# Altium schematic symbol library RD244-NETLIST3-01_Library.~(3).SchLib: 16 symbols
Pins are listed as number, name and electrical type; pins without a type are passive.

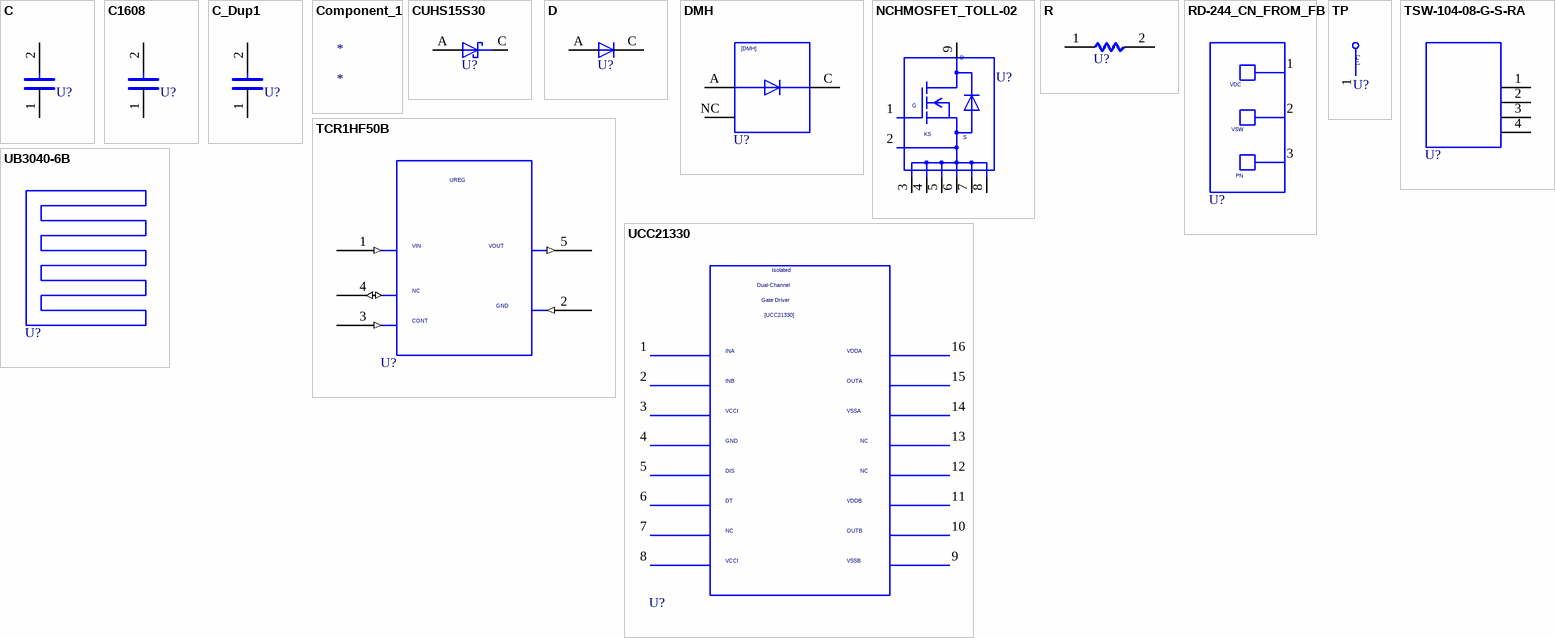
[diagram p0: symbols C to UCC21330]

## C
designator U?  (value not drawn)
OriginalSymbolOrigin: (2540,7620); Altium-Right: 20; Altium-Bottom: 10
pins: 1, 2

## C1608
designator U?  (value not drawn)
TIME: 10:25:11; UPDATEUSER: t4887876; UPDATETIME: 06:19:09; SAVECOUNT: 10; VAL3: xx型名を手入力; VAL1: xxF(x); VAL2: xxV; CHIPSET: 1608; OriginalSymbolOrigin: (2540,7620); Altium-Right: 20
pins: 1, 2

## C_Dup1
designator U?, comment C  (value not drawn)
OriginalSymbolOrigin: (2540,7620); Altium-Right: 20; Altium-Bottom: 10
pins: 1, 2

## Component_1
designator *

## CUHS15S30
designator U?  (value not drawn)
SAVEAREA0: -4630,-153,17114,13055; TIME: 14:49:55; UPDATEUSER: t4887876; UPDATETIME: 17:19:09; SAVECOUNT: 10; OriginalSymbolOrigin: (5080,5080); Altium-Right: 20
pins: A, C

## D
designator U?  (value not drawn)
SAVEAREA0: -225,-91,12804,7836; SAVECOUNT: 3; TIME: 14:49:55; UPDATEUSER: 19870035; UPDATETIME: 14:20:16; OriginalSymbolOrigin: (5080,5080); Altium-Right: 10; Altium-Bottom: 20
pins: A, C

## DMH
designator U?  (value not drawn)
SAVEAREA0: -4931,-287,27399,20979; TIME: 08:58:08; UPDATEUSER: kishi-s; UPDATETIME: 09:01:52; SAVECOUNT: 2; OriginalSymbolOrigin: (5080,17780); Altium-Right: 50; Altium-Bottom: 60
pins: A, C, NC

## NCHMOSFET_TOLL-02
designator U?  (value not drawn)
PARTS: 1; CLASS: DISCRETE; PKG_TYPE: DISC; LEVEL: STD; DEVICENAME: 2SJ132; SAVECOUNT: 33; SAVEAREA0: -7753,-3954,18724,15429; TIME: 17:22:02; UPDATEUSER: t5459927; UPDATETIME: 20:09:04; COMP: NchMOSFET_TOLL-01; CHIPSET: TOLL; VAL3: ※型名を記入する(TOLL); VAL1: ※定格電圧を記入する; VAL2: ※定格電流を記入する; OriginalSymbolOrigin: (0,22860); Altium-Right: 70; Altium-Bottom: 80
pins: 1, 2, 3, 4, 5, 6, 7, 8, 9

## R
designator U?  (value not drawn)
OriginalSymbolOrigin: (5080,5080); Altium-Right: 20
pins: 1, 2

## RD-244_CN_FROM_FB
designator U?, comment RD-244_CN_from_FB  (value not drawn)
TIME: 11:34:46; UPDATEUSER: t5459927; UPDATETIME: 14:01:19; SAVECOUNT: 38; SAVEAREA0: -20981,-344,43891,33349; VAL3: PCB_Pad; OriginalSymbolOrigin: (0,25400); Altium-Right: 50; Altium-Bottom: 100
pins: 1, 2, 3

## TCR1HF50B
designator U?  (value not drawn)
SAVEAREA0: -444,-3509,43701,41525; TIME: 18:31:00; UPDATEUSER: t6860224; UPDATETIME: 18:26:20; SAVECOUNT: 21; VAL1: Linear Regulator; OriginalSymbolOrigin: (7620,35560); Altium-Right: 110; Altium-Bottom: 130
pins: 1 (in), 2 (in), 3 (in), 4 (io), 5 (out)

## TP
designator U?  (value not drawn)
TIME: 16:12:21; UPDATEUSER: fukuda-y; UPDATETIME: 16:18:11; SAVECOUNT: 2; SAVEAREA0: -242,-92,12810,7836; OriginalSymbolOrigin: (0,7620); Altium-Right: 20; Altium-Bottom: 30
pins: 1

## TSW-104-08-G-S-RA
designator U?  (value not drawn)
SAVEAREA0: -8845,-265,28754,23475; SAVECOUNT: 24; TIME: 13:28:28; UPDATEUSER: t4887876; UPDATETIME: 10:06:27; OriginalSymbolOrigin: (2540,20320); Altium-Right: 50; Altium-Bottom: 70
pins: 1, 2, 3, 4

## UB3040-6B
designator U?  (value not drawn)
TIME: 14:03:26; UPDATEUSER: t4887876; UPDATETIME: 11:08:23; SAVECOUNT: 67; SAVEAREA0: -22316,-9081,43667,39223; VAL2: W30mm*L40mm*H6mm; OriginalSymbolOrigin: (5080,21590); Altium-Right: 80; Altium-Bottom: 90

## UCC21330
designator U?  (value not drawn)
SAVEAREA0: -23586,-777,74646,64019; SAVECOUNT: 95; TIME: 14:04:55; UPDATEUSER: t4887876; UPDATETIME: 15:12:35; OriginalSymbolOrigin: (-2540,55880); Altium-Right: 220
pins: 1, 2, 3, 4, 5, 6, 7, 8, 9, 10, 11, 12, 13, 14, 15, 16

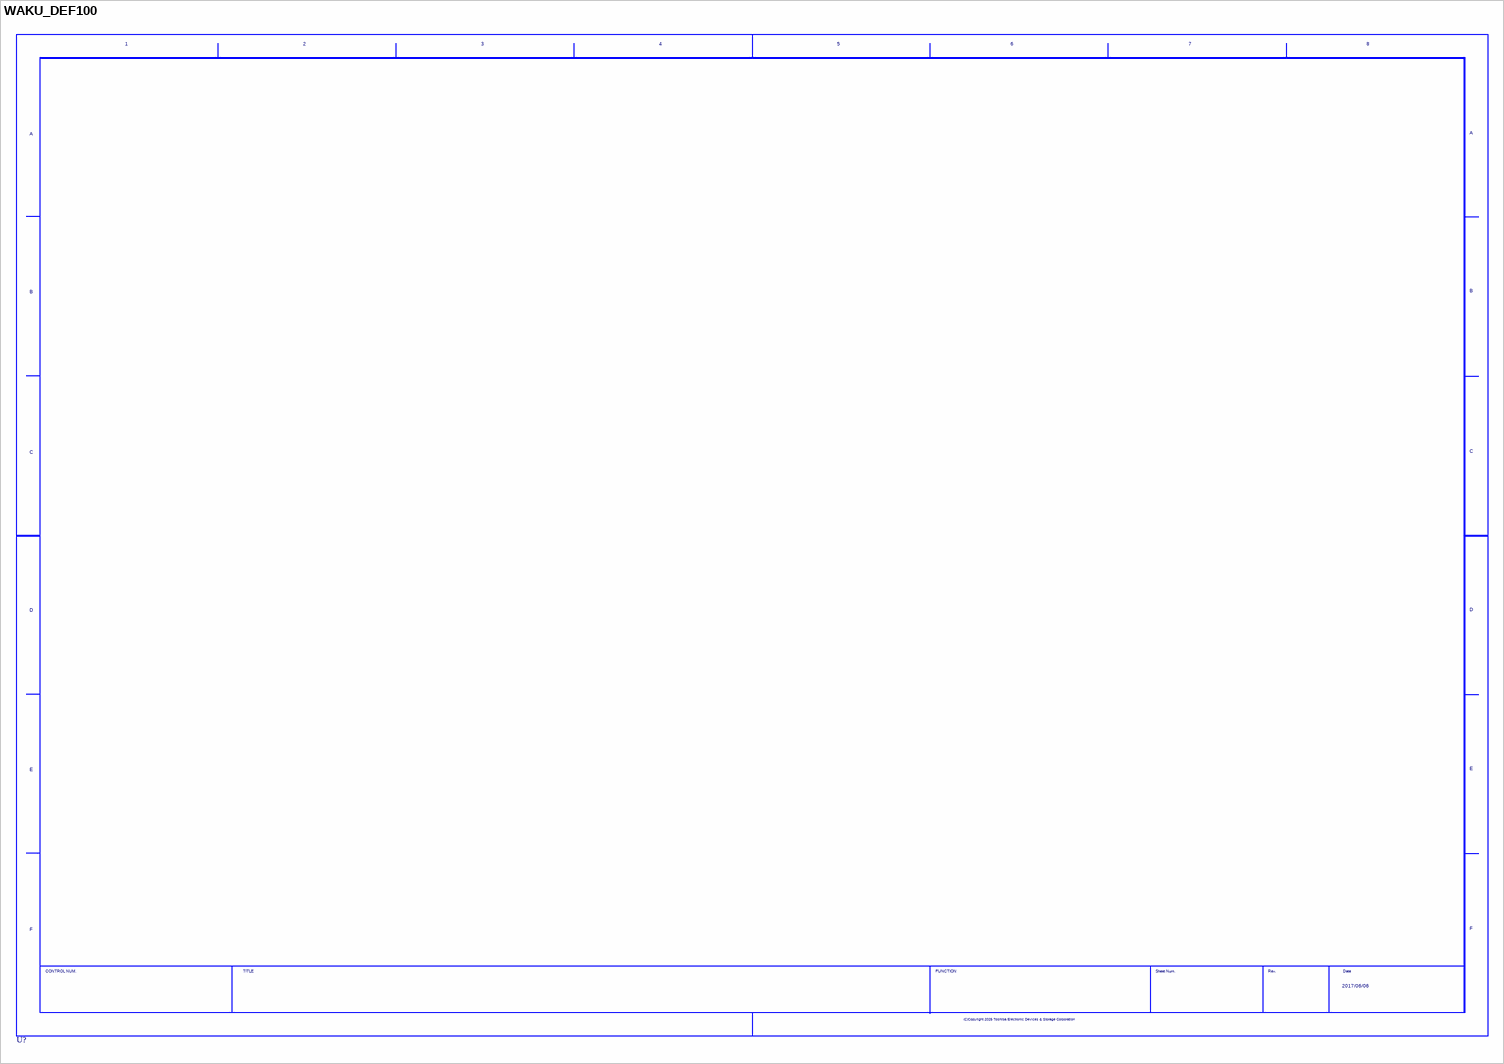
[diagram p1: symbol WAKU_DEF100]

## WAKU_DEF100
designator U?  DATE: 2017/06/06  (hidden comment: WAKU_DEF100)
PLOTTIME: HH:MM; SAVEAREA0: -63393,-16950,474261,314592; TIME: 14:30:25; UPDATEUSER: t5459927; UPDATETIME: 15:40:25; SAVECOUNT: 9; OriginalSymbolOrigin: (10160,284480); Altium-Right: 1570; Altium-Bottom: 1070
